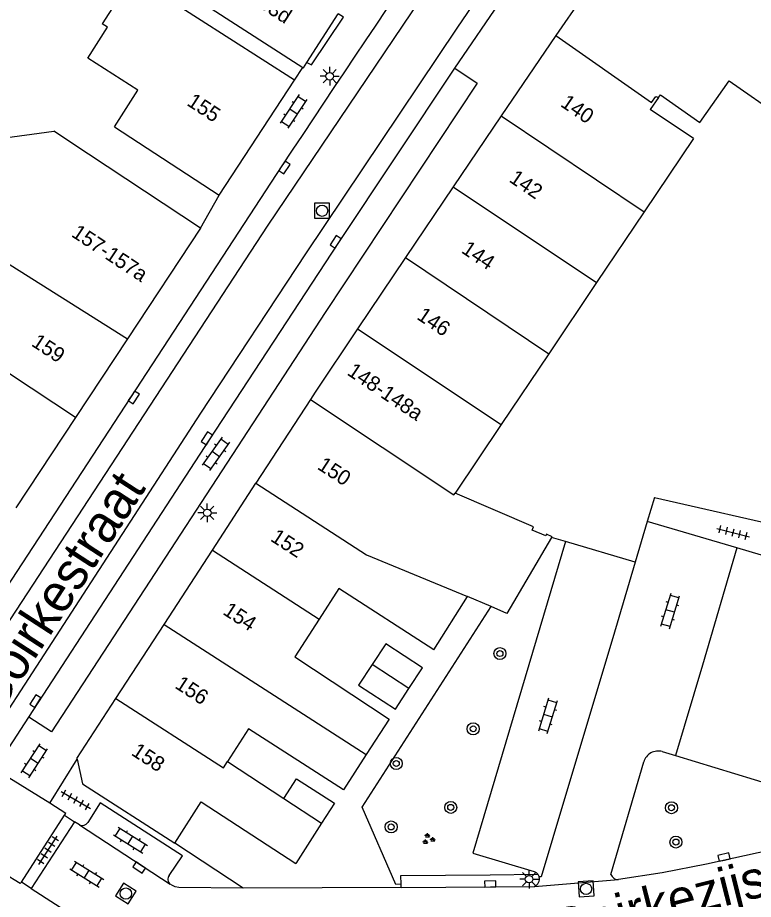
# Model space of a CAD drawing. Extents: x 132998 to 136004, y 396998 to 398512.
# Drawn here: x 133467.1 to 133516.2, y 397809 to 397867.7 of the extents above; entities that cross this region are included whole.
import ezdxf

# ---------------------------------------------------------------- set-up
doc = ezdxf.new("R2010")
doc.units = 0
for name, color, linetype in [('gg-afsc-erfafscheiding', 7, 'Continuous'), ('gg-afsc-muur', 7, 'Continuous'), ('gg-anno-huisnummerreeks BGT', 7, 'Continuous'), ('gg-anno-openbare ruimte label', 7, 'Continuous'), ('gg-bbg-gedigitaliseerde bebouwing', 7, 'Continuous'), ('gg-bbg-gedigitaliseerde bijgebouw', 7, 'Continuous'), ('gg-bbg-hoofdgebouw', 7, 'Continuous'), ('gg-bbg-luifel en loopbrug', 7, 'Continuous'), ('gg-bbg-tussenscheiding', 7, 'Continuous'), ('gg-knt-verharding', 7, 'Continuous'), ('gg-knt-verharding nz', 7, 'Continuous'), ('gt-grn-groengrens', 7, 'Continuous'), ('gt-grn-weggrens', 7, 'Continuous'), ('gt-symb-boom', 7, 'Continuous'), ('gt-symb-groenvak', 7, 'Continuous'), ('gt-symb-klinker verharding', 7, 'Continuous'), ('gt-symb-kolk', 7, 'Continuous'), ('gt-symb-lichtmast', 7, 'Continuous'), ('gt-symb-rioolschacht', 7, 'Continuous'), ('gt-symb-tegel verharding', 7, 'Continuous')]:
    doc.layers.add(name, color=color, linetype=linetype)

# ---------------------------------------------------------------- blocks, each defined once
blk = doc.blocks.new('gt0-KL1')
at = {"layer": 'gt-symb-klinker verharding'}
for p, q in [((-1.15, 0.3), (1.15, 0.3)), ((-1, -0.3), (-1, 0.3)), ((-0.5, 0.3), (-0.5, 0.45)), ((0, -0.3), (0, 0.3)), ((0.5, 0.3), (0.5, 0.45)), ((1, -0.3), (1, 0.3)), ((-1.15, -0.3), (1.15, -0.3)), ((-0.5, -0.45), (-0.5, -0.3)), ((0.5, -0.45), (0.5, -0.3))]:
    blk.add_line(p, q, dxfattribs=at)
blk = doc.blocks.new('gt0-BOOM')
at = {"layer": 'gt-symb-boom'}
for radius in [0.4, 0.2]:
    blk.add_circle((0, 0), radius, dxfattribs=at)
blk = doc.blocks.new('gt0-KOLK')
at = {"layer": 'gt-symb-kolk'}
blk.add_lwpolyline([(0, 0), (0.375, 0), (0.375, 0.4), (-0.375, 0.4), (-0.375, 0), (0, 0)], dxfattribs=at)
blk = doc.blocks.new('gt0-LMAST')
at = {"layer": 'gt-symb-lichtmast'}
for p, q in [((-0.005, 0.246), (-0.005, 0.621)), ((-0.182, 0.173), (-0.447, 0.438)), ((0.172, 0.173), (0.437, 0.438)), ((-0.255, -0.004), (-0.63, -0.004)), ((-0.182, -0.181), (-0.447, -0.446)), ((-0.005, -0.254), (-0.005, -0.629)), ((0.437, -0.446), (0.172, -0.181)), ((0.245, -0.004), (0.62, -0.004))]:
    blk.add_line(p, q, dxfattribs=at)
blk.add_circle((-0.005, -0.004), 0.25, dxfattribs=at)
blk = doc.blocks.new('gt0-RS')
at = {"layer": 'gt-symb-rioolschacht'}
blk.add_lwpolyline([(-0.5, -0.5), (0.5, -0.5), (0.5, 0.5), (-0.5, 0.5)], close=True, dxfattribs=at)
blk.add_circle((0, 0), 0.375, dxfattribs=at)
blk = doc.blocks.new('gt0-GRVAK')
at = {"layer": 'gt-symb-groenvak'}
for p, q in [((-0.11, 0.189), (-0.228, 0.24)), ((-0.182, 0.153), (0.088, 0.153)), ((-0.091, 0.211), (-0.156, 0.322)), ((-0.047, 0.214), (-0.047, 0.393)), ((-0.004, 0.211), (0.061, 0.322)), ((0.015, 0.189), (0.133, 0.24)), ((0.262, -0.052), (0.197, 0.059)), ((0.305, -0.049), (0.305, 0.13)), ((0.349, -0.052), (0.414, 0.059)), ((-0.245, -0.228), (-0.363, -0.177)), ((-0.318, -0.264), (-0.047, -0.264)), ((-0.226, -0.206), (-0.291, -0.095)), ((-0.183, -0.203), (-0.183, -0.024)), ((-0.139, -0.206), (-0.074, -0.095)), ((-0.12, -0.228), (-0.002, -0.177)), ((0.243, -0.074), (0.125, -0.023)), ((0.17, -0.11), (0.441, -0.11)), ((0.368, -0.074), (0.486, -0.023))]:
    blk.add_line(p, q, dxfattribs=at)
blk = doc.blocks.new('gt0-TEG1')
at = {"layer": 'gt-symb-tegel verharding'}
for p, q in [((-1.125, 0), (1.125, 0)), ((-0.9, -0.25), (-0.9, 0.25)), ((-0.45, -0.25), (-0.45, 0.25)), ((0, -0.25), (0, 0.25)), ((0.45, -0.25), (0.45, 0.25)), ((0.9, -0.25), (0.9, 0.25))]:
    blk.add_line(p, q, dxfattribs=at)

msp = doc.modelspace()

# ---------------------------------------------------------------- linework, layer by layer
at = {"layer": 'gg-afsc-erfafscheiding'}
for p, q in [((133509.583, 397835.765), (133509.108, 397834.158)), ((133509.108, 397834.158), (133508.308, 397831.451)), ((133503.664, 397832.824), (133502.734, 397833.099)), ((133508.308, 397831.451), (133503.664, 397832.824))]:
    msp.add_line(p, q, dxfattribs=at)
for points in [[(133509.583, 397835.765), (133519.177, 397833.571), (133520.42, 397836.879)], [(133492.349, 397809.975), (133490.107, 397815.121), (133498.701, 397828.485)]]:
    msp.add_lwpolyline(points, dxfattribs=at)
at = {"layer": 'gg-afsc-muur'}
for p, q in [((133482.187, 397809.728), (133477.63, 397812.73)), ((133492.7, 397809.767), (133482.187, 397809.728)), ((133492.699, 397809.977), (133492.349, 397809.975)), ((133492.7, 397809.767), (133492.699, 397809.977))]:
    msp.add_line(p, q, dxfattribs=at)
at = {"layer": 'gg-bbg-gedigitaliseerde bebouwing'}
for p, q in [((133474.802, 397870.492), (133472.776, 397867.333)), ((133509.861, 397862.422), (133509.298, 397861.616)), ((133461.273, 397859.042), (133469.559, 397860.168)), ((133471.873, 397858.636), (133469.559, 397860.168)), ((133473.597, 397860.467), (133480.59, 397855.9)), ((133479.33, 397853.7), (133471.873, 397858.636))]:
    msp.add_line(p, q, dxfattribs=at)
for points in [[(133514.558, 397863.539), (133518.017, 397861.123), (133522.968, 397868.18)], [(133473.597, 397860.467), (133475.165, 397862.914), (133471.832, 397865.05), (133473.144, 397867.097), (133472.776, 397867.333)], [(133509.861, 397862.422), (133509.985, 397862.6), (133512.618, 397860.761), (133514.558, 397863.539)]]:
    msp.add_lwpolyline(points, dxfattribs=at)
at = {"layer": 'gg-bbg-gedigitaliseerde bijgebouw'}
msp.add_line((133490.767, 397824.621), (133489.857, 397823.244), dxfattribs=at)
for points in [[(133493.225, 397823.03), (133494.121, 397824.415), (133491.676, 397825.998), (133490.767, 397824.621)], [(133489.857, 397823.244), (133492.328, 397821.645), (133493.225, 397823.03)]]:
    msp.add_lwpolyline(points, dxfattribs=at)
at = {"layer": 'gg-bbg-hoofdgebouw'}
for p, q in [((133509.714, 397876.308), (133503.025, 397866.545)), ((133485.6, 397863.57), (133474.802, 397870.492)), ((133486.424, 397864.757), (133488.513, 397867.998)), ((133503.025, 397866.545), (133499.365, 397861.202)), ((133486.196, 397864.403), (133486.424, 397864.757)), ((133486.159, 397864.427), (133486.196, 397864.403)), ((133480.59, 397855.9), (133485.6, 397863.57)), ((133499.365, 397861.202), (133496.166, 397856.474)), ((133512.186, 397859.675), (133509.298, 397861.616)), ((133512.186, 397859.675), (133508.912, 397854.804)), ((133496.166, 397856.474), (133492.996, 397851.748)), ((133508.912, 397854.804), (133505.736, 397850.079)), ((133479.33, 397853.7), (133474.475, 397846.339)), ((133492.996, 397851.748), (133489.807, 397846.996)), ((133505.736, 397850.079), (133502.551, 397845.34)), ((133474.475, 397846.339), (133471.01, 397841.087)), ((133502.551, 397845.34), (133499.381, 397840.624)), ((133486.667, 397842.299), (133483.031, 397836.708)), ((133471.01, 397841.087), (133467.035, 397835.06)), ((133499.381, 397840.624), (133496.304, 397836.045)), ((133480.128, 397832.244), (133483.031, 397836.708)), ((133502.734, 397833.099), (133499.757, 397828.031)), ((133476.913, 397827.3), (133480.128, 397832.244)), ((133494.895, 397825.611), (133497.14, 397829.156)), ((133498.701, 397828.485), (133497.14, 397829.156)), ((133499.757, 397828.031), (133498.701, 397828.485)), ((133473.698, 397822.356), (133476.913, 397827.3)), ((133471.1, 397818.36), (133473.698, 397822.356)), ((133471.1, 397818.36), (133471.109, 397818.319)), ((133481.138, 397818.17), (133484.892, 397815.706)), ((133484.892, 397815.706), (133487.406, 397814.056)), ((133487.406, 397814.056), (133485.68, 397811.354))]:
    msp.add_line(p, q, dxfattribs=at)
for points in [[(133480.753, 397874.416), (133477.791, 397869.821), (133486.159, 397864.427)], [(133489.807, 397846.996), (133486.982, 397842.784), (133486.667, 397842.299)], [(133502.734, 397833.099), (133502.762, 397833.146), (133502.392, 397833.307), (133502.351, 397833.209), (133501.437, 397833.59), (133501.524, 397833.802), (133496.304, 397836.045)], [(133494.895, 397825.611), (133488.552, 397829.697), (133487.24, 397827.658)], [(133487.24, 397827.658), (133485.616, 397825.133), (133491.899, 397820.983), (133490.377, 397818.618)], [(133490.377, 397818.618), (133488.863, 397816.264), (133482.531, 397820.336), (133481.138, 397818.17)], [(133471.109, 397818.319), (133471.46, 397816.67), (133477.63, 397812.73)], [(133477.63, 397812.73), (133479.387, 397815.475), (133485.68, 397811.354)]]:
    msp.add_lwpolyline(points, dxfattribs=at)
at = {"layer": 'gg-bbg-luifel en loopbrug'}
msp.add_lwpolyline([(133484.892, 397815.706), (133485.722, 397817.009), (133488.258, 397815.392), (133487.406, 397814.056)], dxfattribs=at)
at = {"layer": 'gg-bbg-tussenscheiding'}
for p, q in [((133499.365, 397861.202), (133508.912, 397854.804)), ((133496.166, 397856.474), (133505.736, 397850.079)), ((133459.485, 397855.773), (133474.475, 397846.339)), ((133492.996, 397851.748), (133502.551, 397845.34)), ((133489.807, 397846.996), (133499.381, 397840.624)), ((133480.128, 397832.244), (133487.24, 397827.658)), ((133476.913, 397827.3), (133490.377, 397818.618)), ((133493.225, 397823.03), (133490.767, 397824.621))]:
    msp.add_line(p, q, dxfattribs=at)
for points in [[(133503.025, 397866.545), (133509.389, 397862.08), (133509.677, 397862.492), (133509.861, 397862.422)], [(133471.01, 397841.087), (133463.639, 397845.95), (133461.294, 397847.454)], [(133486.667, 397842.299), (133496.229, 397835.934), (133496.304, 397836.045)], [(133483.031, 397836.708), (133490.402, 397831.936), (133497.14, 397829.156)], [(133473.698, 397822.356), (133480.86, 397817.738), (133481.138, 397818.17)]]:
    msp.add_lwpolyline(points, dxfattribs=at)
at = {"layer": 'gg-knt-verharding'}
for p, q in [((133496.294, 397864.365), (133499.785, 397869.506)), ((133485.6, 397863.57), (133486.159, 397864.427)), ((133479.33, 397853.7), (133480.59, 397855.9)), ((133515.081, 397832.397), (133509.108, 397834.158)), ((133519.274, 397831.164), (133515.081, 397832.397)), ((133465.628, 397817.639), (133467.892, 397821.115)), ((133469.416, 397820.15), (133467.892, 397821.115)), ((133510.112, 397818.821), (133510.987, 397818.554)), ((133469.29, 397815.376), (133471.109, 397818.319)), ((133510.987, 397818.554), (133518.736, 397816.194)), ((133506.688, 397810.636), (133508.881, 397818.132)), ((133467.402, 397810.125), (133470.261, 397814.58)), ((133470.928, 397814.15), (133468.04, 397809.702)), ((133470.261, 397814.58), (133470.928, 397814.15)), ((133471.273, 397813.946), (133470.928, 397814.15)), ((133501.822, 397810.645), (133501.904, 397810.465)), ((133468.04, 397809.702), (133467.402, 397810.125)), ((133501.59, 397809.842), (133507.188, 397810.287)), ((133468.04, 397809.702), (133473.926, 397805.947))]:
    msp.add_line(p, q, dxfattribs=at)
for points in [[(133486.424, 397864.757), (133486.725, 397864.598), (133488.858, 397867.775), (133488.513, 397867.998)], [(133467.892, 397821.115), (133479.93, 397839.591), (133488.515, 397852.685), (133496.294, 397864.365)], [(133496.294, 397864.365), (133497.774, 397863.374), (133487.638, 397848.086), (133469.416, 397820.15)], [(133484.763, 397857.862), (133464.178, 397826.413), (133462.868, 397824.392), (133460.691, 397821.034)], [(133503.664, 397832.824), (133497.475, 397812.044), (133501.573, 397810.835), (133501.714, 397810.758), (133501.822, 397810.645)], [(133470.261, 397814.58), (133470.356, 397814.689), (133469.29, 397815.376)], [(133477.257, 397810.568), (133478.131, 397811.876), (133472.642, 397815.402), (133471.816, 397814.103)], [(133517.412, 397812.278), (133513.047, 397811.329), (133510.099, 397810.745), (133507.188, 397810.287)], [(133467.402, 397810.125), (133467.308, 397810.035), (133466.228, 397810.707)], [(133482.187, 397809.728), (133477.891, 397809.761), (133477.65, 397809.814), (133477.479, 397809.894), (133477.315, 397809.996)], [(133492.7, 397809.767), (133498.651, 397809.8), (133501.59, 397809.842)]]:
    msp.add_lwpolyline(points, dxfattribs=at)
for centre, radius, start, end in [((134576.429, 397136.967), 1308.214, 144.805367, 146.560747), ((133509.833, 397817.875), 0.986, 73.56478, 164.90736), ((133471.465, 397814.299), 0.402, 241.44709, 330.80572), ((133507.164, 397810.786), 0.499, 197.45431, 272.71561), ((133477.567, 397810.31), 0.403, 140.27172, 231.30813), ((133501.385, 397810.336), 0.535, 292.52432, 13.97829)]:
    msp.add_arc(centre, radius, start, end, dxfattribs=at)
at = {"layer": 'gg-knt-verharding nz'}
msp.add_line((133471.273, 397813.946), (133477.315, 397809.996), dxfattribs=at)
for points in [[(133518.685, 397904.525), (133517.409, 397902.764), (133514.774, 397899.064), (133503.059, 397882.427), (133483.776, 397853.843), (133462.162, 397820.809), (133461.811, 397820.264)], [(133521.32, 397902.713), (133517.565, 397897.52), (133514.966, 397893.873), (133506.948, 397882.532), (133496.425, 397867.039), (133486.322, 397851.989), (133479.325, 397841.37), (133464.442, 397818.455)], [(133515.081, 397832.397), (133512.781, 397824.581), (133510.987, 397818.554)], [(133508.308, 397831.451), (133506.818, 397826.412), (133503.588, 397815.673), (133502.046, 397810.481), (133501.904, 397810.465)]]:
    msp.add_lwpolyline(points, dxfattribs=at)
at = {"layer": 'gt-grn-groengrens'}
msp.add_lwpolyline([(133492.699, 397809.977), (133492.696, 397810.567), (133498.643, 397810.6), (133501.822, 397810.645)], dxfattribs=at)
at = {"layer": 'gt-grn-weggrens'}
msp.add_line((133469.29, 397815.376), (133465.628, 397817.639), dxfattribs=at)

# ---------------------------------------------------------------- block references
at = {"layer": 'gt-symb-boom'}
for p in [(133499.294, 397825.357), (133497.508, 397820.34), (133492.385, 397818.028), (133496.011, 397815.105), (133510.724, 397815.082), (133492.041, 397813.802), (133511.018, 397812.791)]:
    msp.add_blockref('gt0-BOOM', p, dxfattribs=at)
at = {"layer": 'gt-symb-groenvak'}
msp.add_blockref('gt0-GRVAK', (133494.506, 397812.993), dxfattribs=at)
at = {"layer": 'gt-symb-klinker verharding'}
for p, rotation in [((133485.533, 397861.496), -123.57881372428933), ((133480.358, 397838.673), -125.23135738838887), ((133510.644, 397828.193), 73.01526746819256), ((133502.496, 397821.209), 73.01526746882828), ((133468.266, 397818.203), 56.91369260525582), ((133474.667, 397812.922), -31.798912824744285), ((133471.756, 397810.655), -31.798912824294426)]:
    msp.add_blockref('gt0-KL1', p, dxfattribs=dict(at, rotation=rotation))
at = {"layer": 'gt-symb-kolk'}
for p, rotation in [((133484.763, 397857.862), -123.08630739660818), ((133488.515, 397852.685), 56.834400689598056), ((133474.726, 397842.54), -123.03828460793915), ((133479.93, 397839.591), 56.91369260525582), ((133468.498, 397822.079), 57.867104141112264), ((133514.257, 397811.594), 12.298855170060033), ((133475.361, 397811.263), 146.7071514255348), ((133498.651, 397809.8), 0.8020885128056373)]:
    msp.add_blockref('gt0-KOLK', p, dxfattribs=dict(at, rotation=rotation))
at = {"layer": 'gt-symb-lichtmast'}
for p in [(133487.949, 397863.837), (133479.793, 397834.738), (133501.237, 397810.324)]:
    msp.add_blockref('gt0-LMAST', p, dxfattribs=at)
at = {"layer": 'gt-symb-rioolschacht'}
msp.add_blockref('gt0-RS', (133487.439, 397854.87), dxfattribs=at)
for p, rotation in [((133474.36, 397809.361), 148.32868147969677), ((133505.033, 397809.668), 4.012171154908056)]:
    msp.add_blockref('gt0-RS', p, dxfattribs=dict(at, rotation=rotation))
at = {"layer": 'gt-symb-tegel verharding'}
for p, rotation in [((133514.833, 397833.42), -14.244742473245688), ((133471.021, 397815.603), -30.128600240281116), ((133469.177, 397812.243), 57.326722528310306)]:
    msp.add_blockref('gt0-TEG1', p, dxfattribs=dict(at, rotation=rotation))

# ---------------------------------------------------------------- texts
at = {"layer": 'gg-anno-huisnummerreeks BGT'}
for s, rotation, p in [('153d', 327.2, (133482.487, 397868.9)), ('155', 326.8, (133478.366, 397861.941)), ('140', 325.6, (133503.263, 397861.877)), ('142', 325.9, (133499.839, 397856.844)), ('157-157a', 326.6, (133470.67, 397853.196)), ('144', 326.1, (133496.657, 397852.117)), ('146', 326.1, (133493.688, 397847.692)), ('159', 326.6, (133468.003, 397845.91)), ('148-148a', 326.2, (133489.044, 397843.976)), ('150', 327, (133487.056, 397837.699)), ('152', 327, (133483.939, 397832.905)), ('154', 327, (133480.76, 397828.017)), ('156', 327, (133477.565, 397823.104)), ('158', 327, (133474.659, 397818.635))]:
    msp.add_text(s, height=1, rotation=rotation, dxfattribs=at).set_placement(p)
at = {"layer": 'gg-anno-openbare ruimte label'}
for s, rotation, p in [('Goirkestraat', 57, (133465.814, 397821.119)), ('Goirkezijstraat', 14.1, (133503.033, 397805.694))]:
    msp.add_text(s, height=2.5, rotation=rotation, dxfattribs=at).set_placement(p)

doc.saveas('drawing.dxf')
